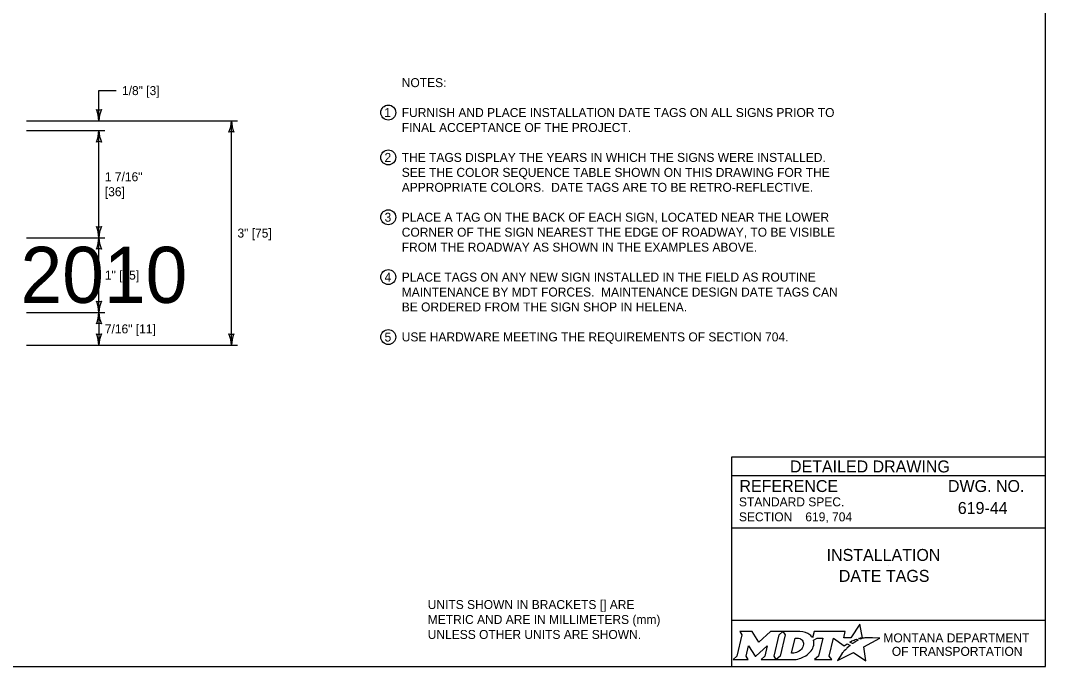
# Model space of a CAD drawing. Extents: x 49991.4 to 50021, y 49987.6 to 50011.4.
# Drawn here: x 50014.08 to 50020.94, y 49999.89 to 50004.2 of the extents above; entities that cross this region are included whole.
import ezdxf

# ---------------------------------------------------------------- set-up
doc = ezdxf.new("R2010")
doc.units = 0
for name, color, linetype in [('Default', 7, 'Continuous'), ('Level 1', 7, 'Continuous'), ('Level 2', 7, 'Continuous'), ('Level 3', 7, 'Continuous'), ('Level 4', 7, 'Continuous')]:
    doc.layers.add(name, color=color, linetype=linetype)

msp = doc.modelspace()

# ---------------------------------------------------------------- linework, layer by layer
at = {"layer": 'Default'}
for points in [[(50019.7003, 50000.0679), (50019.69, 50000.0735), (50019.7016, 50000.0763), (50019.7132, 50000.0783), (50019.6958, 50000.1684), (50019.6363, 50000.0771), (50019.589, 50000.0764), (50019.5993, 50000.1205), (50019.3901, 50000.1206), (50019.38, 50000.0781), (50019.3742, 50000.0864)], [(50018.8933, 50000.1206), (50018.9074, 50000.0972), (50018.8739, 49999.9539), (50018.8482, 49999.9314), (50018.9498, 49999.9314), (50018.9363, 49999.9542), (50018.9525, 50000.0243), (50018.9962, 49999.9553), (50019.0015, 49999.9553), (50019.0766, 50000.0248), (50019.0602, 49999.9537), (50019.0355, 49999.9317), (50019.1371, 49999.9317), (50019.1233, 49999.955), (50019.1565, 50000.0974)], [(50019.1565, 50000.0974), (50019.1818, 50000.1206), (50019.0994, 50000.1206), (50019.0198, 50000.0476), (50018.9753, 50000.1203), (50018.8933, 50000.1206)], [(50019.2954, 50000.1206), (50019.1818, 50000.1206), (50019.1965, 50000.0977), (50019.1626, 49999.9539), (50019.1371, 49999.9317), (50019.2477, 49999.9317)], [(50019.3194, 50000.0339), (50019.3182, 50000.0258), (50019.315, 50000.0165), (50019.3108, 50000.0083), (50019.3052, 50000.0008), (50019.2987, 49999.9939), (50019.2908, 49999.9876), (50019.2825, 49999.9829), (50019.2734, 49999.979), (50019.2643, 49999.9767), (50019.2551, 49999.9758), (50019.2392, 49999.9758), (50019.2628, 50000.0758), (50019.2788, 50000.0758), (50019.2864, 50000.0752), (50019.294, 50000.0733), (50019.3006, 50000.0703), (50019.3067, 50000.0661), (50019.3115, 50000.0611), (50019.3152, 50000.0551), (50019.3179, 50000.0489), (50019.3195, 50000.0415), (50019.3195, 50000.0385), (50019.3194, 50000.0339)], [(50019.3868, 50000.0615), (50019.4114, 50000.0746), (50019.4483, 50000.0746), (50019.4197, 49999.9541), (50019.3922, 49999.9314), (50019.5084, 49999.9314), (50019.4914, 49999.9543), (50019.5196, 50000.0745), (50019.5909, 50000.0228), (50019.612, 50000.0379), (50019.6317, 50000.027)], [(50019.5759, 49999.9711), (50019.5606, 49999.9467), (50019.5559, 49999.9392), (50019.5501, 49999.9306), (50019.5478, 49999.9263), (50019.6531, 49999.9794), (50019.737, 49999.9243), (50019.7239, 50000.017), (50019.8308, 50000.0754), (50019.7815, 50000.0762), (50019.7514, 50000.0766), (50019.7306, 50000.0769), (50019.7238, 50000.0754), (50019.7189, 50000.0742), (50019.7105, 50000.0719), (50019.7003, 50000.0679)], [(50019.6499, 50000.0403), (50019.6475, 50000.0386), (50019.6292, 50000.0482), (50019.6395, 50000.0539), (50019.6436, 50000.0561), (50019.6522, 50000.0601), (50019.6579, 50000.0627), (50019.6658, 50000.0657), (50019.6731, 50000.0684), (50019.6849, 50000.061), (50019.6809, 50000.0589), (50019.6763, 50000.0564), (50019.6721, 50000.0542), (50019.6671, 50000.0513), (50019.6652, 50000.0502), (50019.6625, 50000.0486), (50019.66, 50000.0472), (50019.6577, 50000.0456), (50019.6551, 50000.0438), (50019.6524, 50000.042), (50019.6499, 50000.0403)], [(50019.2934, 49999.939), (50019.3018, 49999.9416), (50019.3148, 49999.947), (50019.3352, 49999.958)], [(50019.5898, 49999.9872), (50019.5898, 49999.9872)]]:
    msp.add_lwpolyline(points, dxfattribs=at)
for centre, radius, start, end in [((50019.3185, 50000.0422), 0.0709, 339.53292, 15.85821), ((50019.2745, 50000.0595), 0.1183, 300.91025, 339.13831)]:
    msp.add_arc(centre, radius, start, end, dxfattribs=at)
for centre, major_axis, ratio, start_param, end_param in [((50019.2933, 50000.0732), (0.0834, -0.0037), 0.568097, 0.61298, 1.570796), ((50019.3489, 50000.0805), (0.0361, -0.0295), 0.469099, 1.225588, 1.570796), ((50019.6206, 50000.0173), (-0.0112, -0.0097), 0.021651, 3.157348, 6.283185), ((50019.5829, 49999.9791), (-0.00694, -0.00806), 0.008222, 0, 3.137361), ((50019.5996, 49999.9974), (-0.0098, -0.0102), 0.016458, 3.141593, 6.279097), ((50019.248, 50000.08), (0, 0.1484), 0.987302, 3.139398, 3.456847)]:
    msp.add_ellipse(centre, major_axis=major_axis, ratio=ratio, start_param=start_param, end_param=end_param, dxfattribs=at)
at = {"layer": 'Level 1'}
msp.add_lwpolyline([(50020.9378, 50008.1646), (50009.7374, 50008.1646), (50009.7374, 49999.8856), (50020.9378, 49999.8856)], close=True, dxfattribs=at)
at = {"layer": 'Level 2'}
for centre in [(50016.5431, 50003.5892), (50016.5431, 50003.2892), (50016.5431, 50002.8892), (50016.5431, 50002.4892), (50016.5431, 50002.0884)]:
    msp.add_circle(centre, 0.0501, dxfattribs=at)
at = {"layer": 'Level 3'}
for p, q in [((50014.6078, 50003.5334), (50014.6078, 50003.7358)), ((50014.6078, 50003.7358), (50014.7224, 50003.7358)), ((50014.1233, 50003.5334), (50015.5345, 50003.5334)), ((50015.4945, 50002.0334), (50015.4945, 50003.5334)), ((50014.1233, 50003.4682), (50014.6478, 50003.4682)), ((50014.6078, 50002.7515), (50014.6078, 50003.4682)), ((50014.1233, 50002.7521), (50014.6478, 50002.7521)), ((50014.6078, 50002.2521), (50014.6078, 50002.7521)), ((50014.1233, 50002.2521), (50014.6078, 50002.2521)), ((50014.6078, 50002.2521), (50014.6078, 50002.0334)), ((50014.6078, 50002.2521), (50014.6478, 50002.2521)), ((50014.1233, 50002.0334), (50015.5345, 50002.0334))]:
    msp.add_line(p, q, dxfattribs=at)
for centre, radius, start, end in [((50014.6078, 50003.6616), 0.0548, 252.13882, 287.86118), ((50014.3751, 50003.5219), 0.233, 2.82731, 22.07716), ((50014.8299, 50003.5242), 0.2223, 157.45601, 177.63952), ((50015.2723, 50003.5426), 0.2223, 337.45601, 357.63952), ((50015.7272, 50003.5449), 0.233, 182.82731, 202.07716), ((50014.3857, 50003.4774), 0.2223, 337.45601, 357.63952), ((50014.8405, 50003.4797), 0.233, 182.82731, 202.07716), ((50015.4945, 50003.4052), 0.0548, 72.13882, 107.86118), ((50014.6078, 50003.34), 0.0548, 72.13882, 107.86118), ((50014.6078, 50002.8803), 0.0548, 252.13882, 287.86118), ((50014.3751, 50002.7406), 0.233, 2.82731, 22.07716), ((50014.8299, 50002.7429), 0.2223, 157.45601, 177.63952), ((50014.3857, 50002.7613), 0.2223, 337.45601, 357.63952), ((50014.8405, 50002.7636), 0.233, 182.82731, 202.07716), ((50014.6078, 50002.6239), 0.0548, 72.13882, 107.86118), ((50014.6078, 50002.3803), 0.0548, 252.13882, 287.86118), ((50014.3751, 50002.2406), 0.233, 2.82731, 22.07716), ((50014.8299, 50002.2429), 0.2223, 157.45601, 177.63952), ((50014.3857, 50002.2613), 0.2223, 337.45601, 357.63952), ((50014.8405, 50002.2636), 0.233, 182.82731, 202.07716), ((50014.6078, 50002.1239), 0.0548, 72.13882, 107.86118), ((50014.6078, 50002.1616), 0.0548, 252.13882, 287.86118), ((50014.3751, 50002.0219), 0.233, 2.82731, 22.07716), ((50014.8299, 50002.0242), 0.2223, 157.45601, 177.63952), ((50015.4945, 50002.1616), 0.0548, 252.13882, 287.86118), ((50015.2618, 50002.0219), 0.233, 2.82731, 22.07716), ((50015.7166, 50002.0242), 0.2223, 157.45601, 177.63952)]:
    msp.add_arc(centre, radius, start, end, dxfattribs=at)
at = {"layer": 'Level 4'}
for p, q in [((50020.9378, 50001.2856), (50018.8378, 50001.2856)), ((50018.8378, 50001.2856), (50018.8378, 49999.8856)), ((50020.9378, 50001.1606), (50018.8378, 50001.1606)), ((50020.5739, 50000.9455), (50020.5739, 50000.9455)), ((50019.3321, 50000.8861), (50019.3321, 50000.8861)), ((50020.9378, 50000.8106), (50018.8378, 50000.8106)), ((50019.8878, 50000.5615), (50019.8878, 50000.5615)), ((50020.9378, 50000.1925), (50018.8378, 50000.1925))]:
    msp.add_line(p, q, dxfattribs=at)

# ---------------------------------------------------------------- texts
at = {"layer": 'Default'}
for s, p in [('MONTANA DEPARTMENT', (50019.854, 50000.0468)), ('OF TRANSPORTATION', (50019.9102, 49999.9568))]:
    msp.add_text(s, height=0.06, dxfattribs=at).set_placement(p)
at = {"layer": 'Level 1'}
msp.add_text('INSTALLED 2010', height=0.375, dxfattribs=at).set_placement((50011.2133, 50002.3166))
at = {"layer": 'Level 2'}
for s, height, p in [('NOTES:', 0.06, (50016.6332, 50003.7592)), ('1/8" [3]', 0.06, (50014.7624, 50003.7058)), ('1', 0.06, (50016.516, 50003.5593)), ('FURNISH AND PLACE INSTALLATION DATE TAGS ON ALL SIGNS PRIOR TO', 0.06, (50016.6332, 50003.5592)), ('FINAL ACCEPTANCE OF THE PROJECT.', 0.06, (50016.6332, 50003.4592)), ('2', 0.06, (50016.5182, 50003.2592)), ('THE TAGS DISPLAY THE YEARS IN WHICH THE SIGNS WERE INSTALLED.', 0.06, (50016.6332, 50003.2592)), ('1 7/16"', 0.06, (50014.6478, 50003.1299)), ('SEE THE COLOR SEQUENCE TABLE SHOWN ON THIS DRAWING FOR THE', 0.06, (50016.6332, 50003.1592)), ('APPROPRIATE COLORS.  DATE TAGS ARE TO BE RETRO-REFLECTIVE.', 0.06, (50016.6332, 50003.0592)), ('[36]', 0.06, (50014.6478, 50003.0299)), ('3', 0.06, (50016.5182, 50002.8592)), ('PLACE A TAG ON THE BACK OF EACH SIGN, LOCATED NEAR THE LOWER', 0.06, (50016.6332, 50002.8592)), ('3" [75]', 0.06, (50015.5345, 50002.7534)), ('CORNER OF THE SIGN NEAREST THE EDGE OF ROADWAY, TO BE VISIBLE', 0.06, (50016.6332, 50002.7592)), ('FROM THE ROADWAY AS SHOWN IN THE EXAMPLES ABOVE.', 0.06, (50016.6332, 50002.6592)), ('1" [25]', 0.06, (50014.6478, 50002.4721)), ('4', 0.06, (50016.5182, 50002.4592)), ('PLACE TAGS ON ANY NEW SIGN INSTALLED IN THE FIELD AS ROUTINE', 0.06, (50016.6332, 50002.4592)), ('MAINTENANCE BY MDT FORCES.  MAINTENANCE DESIGN DATE TAGS CAN', 0.06, (50016.6332, 50002.3592)), ('BE ORDERED FROM THE SIGN SHOP IN HELENA.', 0.06, (50016.6332, 50002.2592)), ('7/16" [11]', 0.06, (50014.6478, 50002.1128)), ('5', 0.06, (50016.5182, 50002.0584)), ('USE HARDWARE MEETING THE REQUIREMENTS OF SECTION 704. ', 0.06, (50016.6332, 50002.0592)), ('619-44', 0.08, (50020.3513, 50000.9055)), ('619, 704', 0.06, (50019.3321, 50000.8561)), ('INSTALLATION', 0.08, (50019.4741, 50000.5915)), ('DATE TAGS', 0.08, (50019.5556, 50000.4515)), ('UNITS SHOWN IN BRACKETS [] ARE ', 0.06, (50016.807, 50000.2698)), ('METRIC AND ARE IN MILLIMETERS (mm) ', 0.06, (50016.807, 50000.1698)), ('UNLESS OTHER UNITS ARE SHOWN.', 0.06, (50016.807, 50000.0698))]:
    msp.add_text(s, height=height, dxfattribs=at).set_placement(p)
at = {"layer": 'Level 4'}
for s, height, p in [('DETAILED DRAWING', 0.0799, (50019.2295, 50001.1831)), ('REFERENCE', 0.08, (50018.8914, 50001.0522)), ('DWG. NO.', 0.08, (50020.2856, 50001.0522)), ('STANDARD SPEC.', 0.06, (50018.8881, 50000.9562)), ('SECTION', 0.06, (50018.8881, 50000.8562))]:
    msp.add_text(s, height=height, dxfattribs=at).set_placement(p)

doc.saveas('drawing.dxf')
